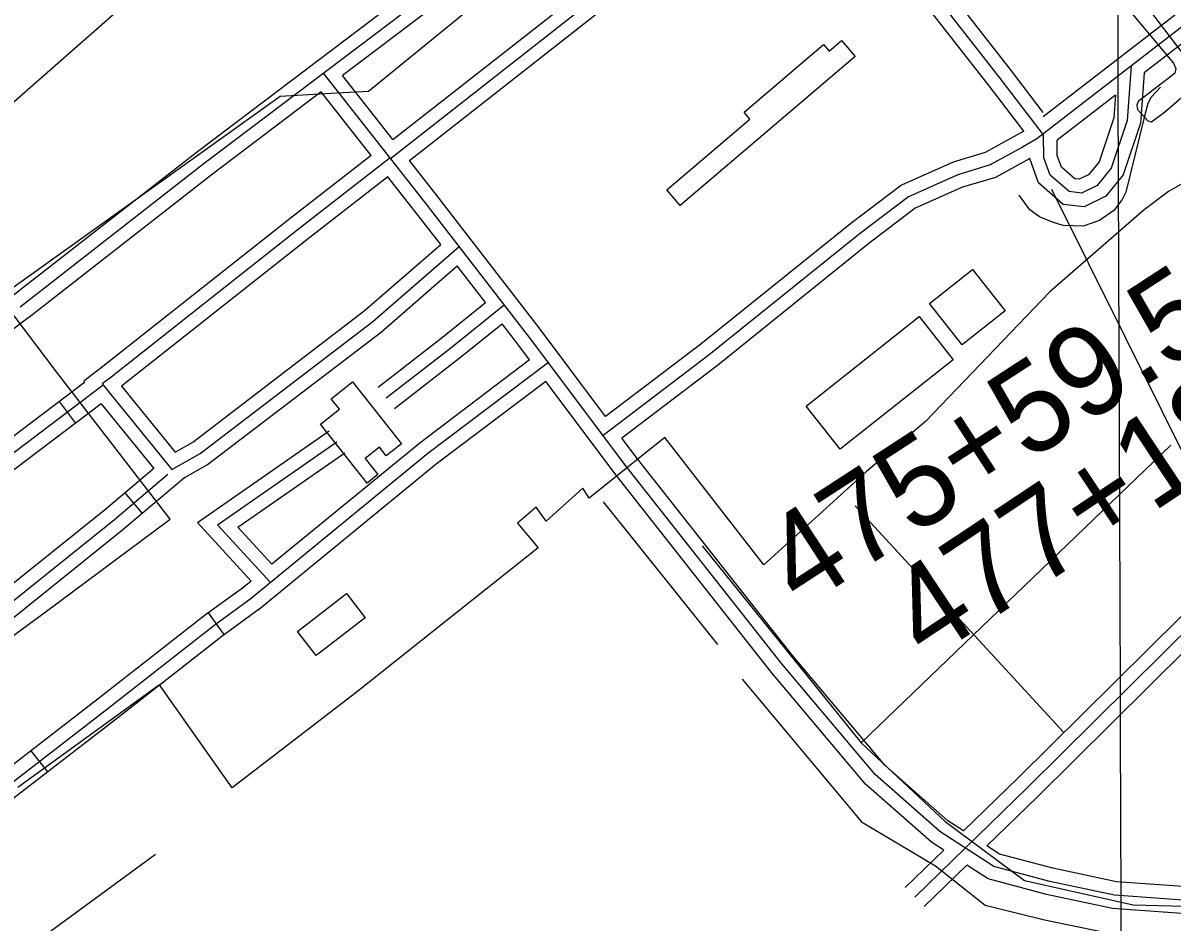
# Model space of a CAD drawing. Extents: x 3405885 to 3443815, y 558517 to 583997.
# Drawn here: x 3411396 to 3412679, y 573242 to 574246 of the extents above; entities that cross this region are included whole.
import ezdxf

# ---------------------------------------------------------------- set-up
doc = ezdxf.new("R2010")
doc.units = 0
for name, color, linetype in [('V-BLDG-OTLN', 7, 'Continuous'), ('V-DOMW-TANK', 7, 'Continuous'), ('V-GRID-MAJR', 7, 'Continuous'), ('V-ROAD-CNTR', 7, 'Continuous'), ('V-SITE-OTLN', 7, 'Continuous'), ('V-SURV-IDEN', 7, 'Continuous'), ('V-TOPO-SHOR', 7, 'Continuous'), ('V-UTIL-LINE', 7, 'Continuous')]:
    doc.layers.add(name, color=color, linetype=linetype)

msp = doc.modelspace()

# ---------------------------------------------------------------- linework, layer by layer
at = {"layer": 'V-BLDG-OTLN'}
for points in [[(3412455.1750000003, 573971.24), (3412491.701, 573925.144), (3412443.883, 573887.254), (3412407.359, 573933.35)], [(3412269.696, 573818.932), (3412395.693, 573918.686), (3412433.753, 573870.618), (3412307.754, 573770.862)], [(3411763.838, 573846.031), (3411818.432, 573776.885), (3411801.3880000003, 573763.429), (3411793.761, 573773.09), (3411777.857, 573760.531), (3411792.066, 573742.536), (3411780.009, 573733.019), (3411728.066, 573798.804), (3411749.24, 573815.522), (3411740.0160000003, 573827.223)], [(3411702.3215575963, 573567.64083831), (3411757.012448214, 573609.9057537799), (3411777.831406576, 573582.966807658), (3411723.141515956, 573540.70089219)]]:
    msp.add_lwpolyline(points, close=True, dxfattribs=at)
at = {"layer": 'V-DOMW-TANK'}
msp.add_lwpolyline([(3412324.3310000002, 574208.9450000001), (3412129.298, 574042.572), (3412114.427, 574060.002), (3412207.019, 574138.988), (3412200.478, 574146.657), (3412289.123, 574222.28), (3412295.56, 574214.735), (3412309.3540000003, 574226.503)], close=True, dxfattribs=at)
at = {"layer": 'V-GRID-MAJR'}
msp.add_spline([(3412655.2120000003, 563916.2490000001), (3412633.177, 569976.235), (3412611.137, 576037.292), (3412589.098, 582098.367), (3412589.094, 582099.421)], degree=3, dxfattribs=at)
at = {"layer": 'V-ROAD-CNTR'}
for p, q in [((3411454.9910522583, 573800.1873732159), (3411436.89008846, 573824.1113253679)), ((3411529.4789032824, 573699.15557528), (3411510.085942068, 573722.0445295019)), ((3411620.8047206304, 573564.132845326), (3411603.1467559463, 573588.3857968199)), ((3411423.864114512, 573410.8601518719), (3411405.5001512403, 573434.5821044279))]:
    msp.add_line(p, q, dxfattribs=at)
for points in [[(3411743.736474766, 575848.64627629), (3411818.126325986, 575748.0604774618), (3412063.7688347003, 575437.8830978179), (3412542.4968772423, 574823.2493270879), (3412747.4744672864, 574558.716856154), (3412816.798328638, 574472.1760292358), (3412845.03727216, 574429.757114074), (3412852.7542567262, 574382.760208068), (3412838.7142848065, 574357.1352593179), (3412804.9533523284, 574328.34931689), (3412717.63252697, 574264.362444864), (3412576.164809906, 574154.8876638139), (3412526.995908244, 574117.0397395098), (3412511.100940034, 574107.7017581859), (3412475.117012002, 574087.92979773), (3412438.9180844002, 574077.026819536), (3412383.797194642, 574052.4998685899), (3412330.3933014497, 574011.927949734), (3412161.545639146, 573876.0032215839), (3412043.2318757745, 573786.2494010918)], [(3412534.229893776, 574146.417680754), (3412497.6509669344, 574194.33458492), (3412358.916244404, 574372.0482294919), (3412197.08856806, 574574.7438241), (3412126.071710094, 574671.747630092), (3412120.26372171, 574691.459590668), (3412127.9137064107, 574701.667570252), (3412151.53865916, 574723.5495264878), (3412300.150361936, 574841.1312913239), (3412431.1001000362, 574941.860089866)], [(3412431.099100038, 574941.861089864), (3412530.651900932, 574814.0473454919), (3412735.6914908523, 574549.4338747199), (3412804.678352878, 574463.3140469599), (3412830.7593007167, 574424.1361253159), (3412837.114288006, 574385.432202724), (3412826.884308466, 574366.760240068), (3412795.641370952, 574340.122293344), (3412708.60754502, 574276.3454208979), (3412566.999828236, 574166.762640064), (3412534.12789398, 574141.458690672)], [(3412632.136697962, 574198.2015771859), (3412627.863706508, 574137.3366989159), (3412609.89274245, 574084.1158053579), (3412594.38277347, 574065.0418435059), (3412577.070808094, 574056.50486058), (3412562.976836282, 574058.141857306), (3412541.868878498, 574076.671820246), (3412534.8618925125, 574095.81478196), (3412534.5258931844, 574121.3117309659), (3412485.7769906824, 574185.1686032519), (3412347.14326795, 574362.7532480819), (3412185.170591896, 574565.6298423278), (3412112.422737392, 574664.99864359), (3412103.749754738, 574694.4355847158), (3412116.7247287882, 574711.749550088), (3412141.77367869, 574734.950503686), (3412290.9233803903, 574852.9582676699)], [(3411806.1853498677, 574095.2607830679), (3412026.8009086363, 574268.0384375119), (3412269.626422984, 574459.8450538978)], [(3411808.735344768, 574116.3097409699), (3412017.527927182, 574279.8284139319), (3412248.4964652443, 574462.270049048)], [(3411827.2533077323, 574092.7077881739), (3412036.07389009, 574256.248461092), (3412267.214427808, 574438.8250959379)], [(3412512.4239373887, 574125.543722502), (3412473.9030144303, 574176.002621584), (3412335.370291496, 574353.4582666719), (3412267.215427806, 574438.8250959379)], [(3412012.984936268, 574429.433114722), (3412000.8459605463, 574412.9671476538), (3411589.395783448, 574101.5147705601), (3411383.8421945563, 573941.2160911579)], [(3412025.05891212, 574420.5321325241), (3412011.6309389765, 574402.318168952), (3411598.53476517, 574089.6197943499), (3411393.0661761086, 573929.3881148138)], [(3412037.132887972, 574411.631150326), (3412022.4159174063, 574391.66919025), (3411752.8114566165, 574187.5885984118)], [(3412703.571785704, 574234.5149455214), (3412646.6296689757, 574190.44959269)], [(3414139.767682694, 573697.4075787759), (3414069.662822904, 573596.0877814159), (3413892.83017657, 573409.71615416), (3413837.968286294, 573368.3172369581), (3413792.2093778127, 573346.5322805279), (3413733.22549578, 573338.4372967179), (3413529.543903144, 573318.2523370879), (3413219.114524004, 573292.0943894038), (3412885.0131922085, 573261.8194499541), (3412799.3063636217, 573260.0774534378), (3412715.563531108, 573266.1924412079), (3412613.74273475, 573273.6114263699), (3412541.528879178, 573288.835395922), (3412479.1230039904, 573305.449362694), (3412418.7961246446, 573344.4352847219), (3412346.802268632, 573407.948157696), (3412242.779476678, 573531.31591096), (3412069.6698228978, 573750.9934716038), (3411960.20904182, 573896.964179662), (3411844.83427257, 574046.002881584), (3411731.588499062, 574190.336592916)], [(3412646.6296689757, 574190.4505926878), (3412642.6916768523, 574134.3637048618), (3412623.2387157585, 574076.7528200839), (3412603.954754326, 574053.0368675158), (3412579.735802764, 574041.0948913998), (3412556.5978490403, 574043.7818860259), (3412529.0979040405, 574067.922837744), (3412519.17792388, 574095.02478354)], [(3411808.7363447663, 574116.310740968), (3411752.8114566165, 574187.5875984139)], [(3411728.8885044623, 574169.47963463), (3411607.6737468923, 574077.72481814), (3411402.29015766, 573917.5601384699)], [(3411784.701392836, 574098.343776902), (3411728.887504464, 574169.4786346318)], [(3412614.8277325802, 574165.8416419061), (3412613.035736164, 574140.3096929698), (3412596.546769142, 574091.478790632), (3412584.8107926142, 574077.046819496), (3412574.4058134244, 574071.9148297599), (3412569.3558235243, 574072.5018285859), (3412554.639852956, 574085.420802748), (3412549.8268625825, 574098.5697764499), (3412549.6038630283, 574115.512742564)], [(3412614.8287325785, 574165.840641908), (3412585.3297915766, 574143.0126875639), (3412549.6038630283, 574115.512742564)], [(3412512.4239373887, 574125.543722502), (3412469.2780236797, 574101.8367699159), (3412433.685094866, 574091.1167913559), (3412376.109210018, 574065.4968425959), (3412321.151319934, 574023.7449261), (3412152.3076576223, 573887.823197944), (3412046.1838698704, 573807.316358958)], [(3411784.701392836, 574098.3447768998), (3411694.432573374, 574028.1459172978), (3411483.580995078, 573861.6582502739), (3411464.0790340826, 573846.707280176), (3411465.061032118, 573845.426282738)], [(3411805.801350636, 574095.7517820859), (3411703.6845548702, 574016.338940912), (3411492.791976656, 573849.819273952), (3411484.7359927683, 573843.643286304), (3411562.276837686, 573748.2784770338), (3411593.855774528, 573766.1934412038), (3411786.501389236, 573913.371146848), (3411882.69419685, 573997.095979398)], [(3412046.1838698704, 573807.31535896), (3411972.1410179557, 573906.05516148), (3411856.665248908, 574055.2238631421), (3411827.2543077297, 574092.708788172)], [(3412519.17792388, 574095.02478354), (3412480.9560003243, 574074.0228255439), (3412444.151073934, 574062.9368477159), (3412391.485179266, 574039.502894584), (3412339.6352829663, 574000.1109733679), (3412170.7836206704, 573864.1832452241), (3412064.182833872, 573783.31540696)], [(3412519.896922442, 574093.060787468), (3412519.896922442, 574093.0597874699)], [(3411803.220355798, 574074.7428241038), (3411712.936536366, 574004.5319645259), (3411506.06495011, 573841.1872912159)], [(3411862.1652379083, 573999.1119753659), (3411833.0032962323, 574036.7819000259), (3411803.2193558, 574074.741824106)], [(3411506.06495011, 573841.1872912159), (3411565.910830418, 573767.5854384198), (3411585.563791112, 573778.734416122), (3411777.01440821, 573925.00012359), (3411862.163237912, 573999.1119753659)], [(3411576.8778084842, 573739.3164949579), (3411602.147757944, 573753.652466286), (3411795.988370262, 573901.7421701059), (3411880.5582011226, 573975.351022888)], [(3411912.243137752, 573934.4221047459), (3411880.5592011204, 573975.3500228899)], [(3411792.2753776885, 573839.953293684), (3411864.1642339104, 573895.8071819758), (3411912.242137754, 573934.4231047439)], [(3411801.478359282, 573828.108317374), (3411873.463215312, 573884.0362055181), (3411933.122095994, 573931.95510968)], [(3411402.149157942, 573917.4511386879), (3411204.818552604, 573767.3004389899), (3411117.4557273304, 573699.999573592)], [(3411810.681340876, 573816.263341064), (3411882.7621967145, 573872.26522906), (3411930.608101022, 573910.6961521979)], [(3411961.3710394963, 573870.4122327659), (3411948.2770656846, 573887.873197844), (3411930.60910102, 573910.6961521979)], [(3411961.3710394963, 573870.413232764), (3411838.7362847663, 573777.6754182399), (3411673.8706144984, 573642.661688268)], [(3411982.33399757, 573867.459238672), (3411848.0152662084, 573765.886441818), (3411648.945664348, 573602.8627678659)], [(3411465.061032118, 573845.426282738), (3411232.4974972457, 573669.4696346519), (3411174.4626133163, 573624.7427241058)], [(3411979.3690035, 573846.4112807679), (3411857.29424765, 573754.0974653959), (3411658.44964534, 573591.257791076)], [(3412423.2121158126, 573323.7223261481), (3412409.71314281, 573332.445308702), (3412336.04829014, 573397.4321787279), (3412231.1514999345, 573521.8369299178), (3412057.776846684, 573741.8504898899), (3411979.3690035, 573846.4102807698)], [(3411485.813990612, 573842.3172889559), (3411241.601479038, 573657.547658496), (3411075.827810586, 573529.7889140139)], [(3411483.3139956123, 573821.6163303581), (3411250.7054608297, 573645.6256823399), (3411192.578577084, 573600.828771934)], [(3411483.3139956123, 573821.6163303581), (3411542.170877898, 573749.2304751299)], [(3411650.6246609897, 573623.6257263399), (3411590.7667807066, 573688.9435957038), (3411737.961486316, 573791.266391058)], [(3412445.3100716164, 573345.160283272), (3412427.879106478, 573356.425260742), (3412357.556247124, 573418.4641366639), (3412254.407453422, 573540.7948920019), (3412081.5627991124, 573760.136453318), (3412064.181833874, 573783.3134069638)], [(3411672.397617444, 573622.067729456), (3411613.4217353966, 573686.423600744), (3411746.523469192, 573778.95041569)], [(3411673.8706144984, 573642.661688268), (3411636.0766900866, 573683.9036057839), (3411755.0854520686, 573766.6344403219)], [(3411053.7268547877, 573340.649292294), (3411181.663598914, 573443.4110867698), (3411347.0562681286, 573571.2748310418), (3411498.29496565, 573692.393588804), (3411557.9298463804, 573742.922487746)], [(3411542.170877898, 573749.2304751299), (3411488.756984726, 573703.9715656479), (3411337.7802866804, 573583.0638074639), (3411253.4814552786, 573517.8929378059)], [(3411576.8778084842, 573739.3164949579), (3411507.8329465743, 573680.8156119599), (3411356.332249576, 573559.48585462), (3411270.7924206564, 573493.3559868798)], [(3414152.102658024, 573688.872595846), (3414081.33979955, 573586.6018003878), (3413902.857156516, 573398.49117661), (3413845.789270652, 573355.427262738), (3413796.55536912, 573331.9883096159), (3413734.98549226, 573323.5383265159), (3413530.912900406, 573303.3143669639), (3413220.42152139, 573277.1514192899), (3412885.843190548, 573246.8334799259), (3412798.9113644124, 573245.06648346), (3412714.47253329, 573251.232471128), (3412611.6407389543, 573258.7244561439), (3412538.0498861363, 573274.2394251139), (3412472.97301629, 573291.5643904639), (3412449.071064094, 573307.0103595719)], [(3412445.3100716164, 573345.160283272), (3412506.2759496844, 573404.3101649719), (3412759.40244343, 573654.8996637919)], [(3412471.1680199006, 573328.449316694), (3412527.273907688, 573382.884207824), (3412778.110406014, 573631.20571118)], [(3411643.5676751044, 573617.814737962), (3411600.0167622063, 573586.1068013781), (3411480.179001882, 573492.3969887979), (3411371.588219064, 573408.329156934), (3411349.69026286, 573391.5721904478)], [(3411650.6246609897, 573623.6257263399), (3411639.441683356, 573614.4677446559)], [(3412390.856180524, 573271.4294307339), (3412516.774928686, 573393.597186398), (3412743.1584759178, 573617.711738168)], [(3410712.2505377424, 573066.9758396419), (3410745.3714715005, 573045.9498816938), (3410767.558427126, 573040.233893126), (3410809.872342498, 573068.09183741), (3410868.86622451, 573123.7147261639), (3410940.3130816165, 573185.118603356), (3410984.486993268, 573220.4525326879), (3411024.4879132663, 573239.935493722), (3411091.417779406, 573230.0615134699), (3411154.2956536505, 573242.614488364), (3411206.802548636, 573262.1264493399), (3411255.801450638, 573300.8413719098), (3411380.7372007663, 573396.4421807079), (3411489.38998346, 573480.558012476), (3411609.053744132, 573574.1318253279), (3411652.396657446, 573605.6887622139)], [(3411661.2256397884, 573593.5627864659), (3411618.090726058, 573562.156849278), (3411498.6009650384, 573468.7190361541), (3411389.8861824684, 573384.5552044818), (3411265.009432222, 573288.9993955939), (3411214.24553375, 573248.890475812), (3411158.4026454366, 573228.1385173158), (3411096.832768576, 573215.8465419)], [(3413931.469715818, 573472.2336761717), (3413882.803196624, 573420.9411317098), (3413830.147301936, 573381.2072111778), (3413787.8633865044, 573361.0762514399), (3413731.4654993, 573353.3362669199), (3413528.1749058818, 573333.190307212), (3413217.8075266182, 573307.0373595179), (3412884.183193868, 573276.805419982), (3412799.701362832, 573275.0884234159), (3412716.654528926, 573281.152411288), (3412615.844730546, 573288.4983965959), (3412545.00787222, 573303.43136673), (3412485.2729916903, 573319.334334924), (3412471.1680199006, 573328.449316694)], [(3412380.411201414, 573282.1954092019), (3412423.2121158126, 573323.7223261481)], [(3412401.3011596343, 573260.663452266), (3412449.071064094, 573307.0103595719)]]:
    msp.add_lwpolyline(points, dxfattribs=at)
at = {"layer": 'V-SITE-OTLN'}
for points in [[(3411294.125, 573496.165), (3411420.849, 573588.979), (3411560.572, 573692.734), (3411433.782, 573857.2930000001), (3411369.989, 573940.725), (3411683.221, 574164.422), (3411746.324, 574168.137), (3411781.613, 574170.254), (3411972.591, 574326.279)], [(3412692.237, 574068.645), (3412673.828, 574058.417), (3412646.661, 574037.679), (3412541.558, 573946.279), (3412403.078, 573801.6680000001), (3412336.938, 573746.177), (3412222.713, 573641.944), (3412112.012, 573783.877), (3412027.87, 573716.233), (3412020.809, 573727.346), (3411979.9250000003, 573690.6410000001), (3411968.568, 573706.337), (3411947.931, 573688.37), (3411970.987, 573660.843), (3411767.881, 573499.336), (3411629.758, 573393.305), (3411548.667, 573508.165), (3411390.541, 573393.405)]]:
    msp.add_lwpolyline(points, dxfattribs=at)
at = {"layer": 'V-TOPO-SHOR'}
for p, q in [((3410936.5111056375, 573762.7158103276), (3411671.825651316, 574409.9463272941)), ((3412543.287066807, 574061.0008433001), (3412726.4826049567, 573692.7818472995)), ((3412043.5691848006, 573712.0769535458), (3412170.861088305, 573552.890590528)), ((3412324.4306538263, 573707.6937441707), (3412556.7234977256, 573455.3127730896))]:
    msp.add_line(p, q, dxfattribs=at)
for points in [[(3412665.11, 574174.52), (3412654.769, 574163.566), (3412650.972, 574156.553), (3412646.5100000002, 574139.463), (3412626.474, 574057.524), (3412622.302, 574049.3470000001), (3412613.1380000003, 574037.243), (3412596.9930000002, 574025.836), (3412578.858, 574019.444), (3412556.3850000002, 574020.363), (3412544.724, 574024.111), (3412529.9420000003, 574030.151), (3412519.403, 574037.784), (3412507.219, 574054.307)], [(3410594.7459985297, 573849.4565432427), (3410960.057685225, 573382.8446805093), (3411203.606152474, 573069.9345534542), (3411544.027529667, 573319.0998181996)], [(3412153.9005540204, 573662.9576194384), (3412330.9946707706, 573443.3962989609), (3412676.592278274, 573775.1834275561)], [(3412198.5485653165, 573514.4541424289), (3412331.3471245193, 573355.28980777), (3412414.1452152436, 573306.0603318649), (3412469.3879991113, 573262.2273698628), (3412535.533952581, 573245.9717430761), (3412667.803831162, 573218.9671452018), (3412833.0695872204, 573203.1080288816), (3413009.1944561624, 573225.8395591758), (3413488.0972751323, 573271.809272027), (3413719.310729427, 573289.2544302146), (3413818.3644469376, 573306.1709077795), (3413895.2373431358, 573361.5458618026), (3414010.524659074, 573450.1149485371), (3414131.2084889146, 573566.2393421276)], [(3412330.9946707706, 573443.3962989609), (3412424.960271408, 573355.6642898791), (3412513.3311029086, 573289.936875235), (3412634.5876700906, 573262.8882206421), (3412805.31602513, 573258.0644440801), (3412976.0003234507, 573264.2539789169), (3413168.66718785, 573281.5449385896), (3413614.5300726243, 573327.3824812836), (3413741.0950402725, 573349.9157563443), (3413845.4351298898, 573421.9208192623), (3413889.31214861, 573466.1502917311)]]:
    msp.add_lwpolyline(points, dxfattribs=at)
at = {"layer": 'V-UTIL-LINE'}
for points in [[(3412864.46, 573981.132), (3412741.578, 574143.9500000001), (3412704.7630000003, 574191.689), (3412692.745, 574208.525), (3412596.293, 574335.327), (3412501.8140000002, 574461.756), (3412398.589, 574594.403), (3412366.978, 574635.492), (3412375.9790000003, 574642.296), (3412314.74, 574723.313)], [(3412297.987, 574703.404), (3412349.576, 574639.25), (3412342.929, 574633.655), (3412354.938, 574617.607), (3412378.1520000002, 574587.082), (3412373.077, 574581.8960000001), (3412545.103, 574362.398), (3412679.409, 574201.282), (3412682.233, 574195.394), (3412681.105, 574190.251), (3412675.237, 574185.453), (3412640.0160000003, 574158.638), (3412638.48, 574154.677), (3412639.325, 574149.555), (3412650.903, 574137.054), (3412654.859, 574135.9130000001), (3412669.343, 574146.723), (3412696.3170000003, 574169.898), (3412701.437, 574170.742), (3412704.611, 574169.198), (3412720.205, 574150.032), (3412863.1410000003, 573964.3420000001)]]:
    msp.add_lwpolyline(points, dxfattribs=at)

# ---------------------------------------------------------------- texts
at = {"layer": 'V-SURV-IDEN'}
for s, height, rotation, p in [('475+59.5', 100.00000000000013, 33.05010114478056, (3412264.424190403, 573591.8625720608)), ('477+18.2', 100.00000000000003, 33.588978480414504, (3412404.7261886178, 573532.8127213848))]:
    msp.add_text(s, height=height, rotation=rotation, dxfattribs=at).set_placement(p)

doc.saveas('drawing.dxf')
